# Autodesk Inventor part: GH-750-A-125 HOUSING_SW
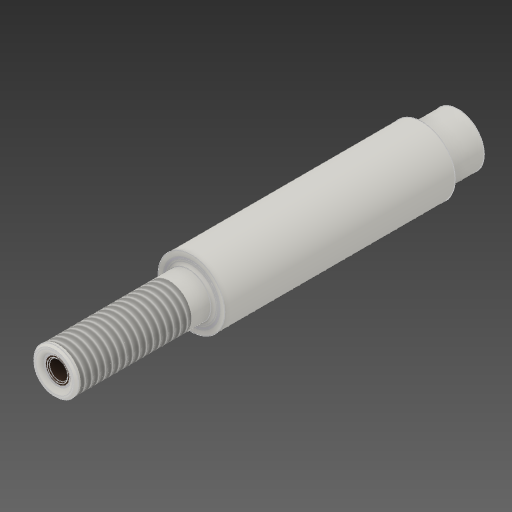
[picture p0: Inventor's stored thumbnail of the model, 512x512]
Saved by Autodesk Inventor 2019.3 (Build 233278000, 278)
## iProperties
Created: 2018-11
Part Number: GH-750-A-125 HOUSING_SW
Material: Generic
Document SubType Name: Modeling
Designer: Justin
Density: 1 g/cm^3
Appearance: Default
Author: Justin
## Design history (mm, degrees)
node "Assembly1"
body "Solid1"
node "Part1:1"
node "Part2:1"
body "Solid2"
node "Part3:1"
body "Solid3"
node "Part4:1"
body "Solid4"
node "Part5:1"
body "Solid5"
